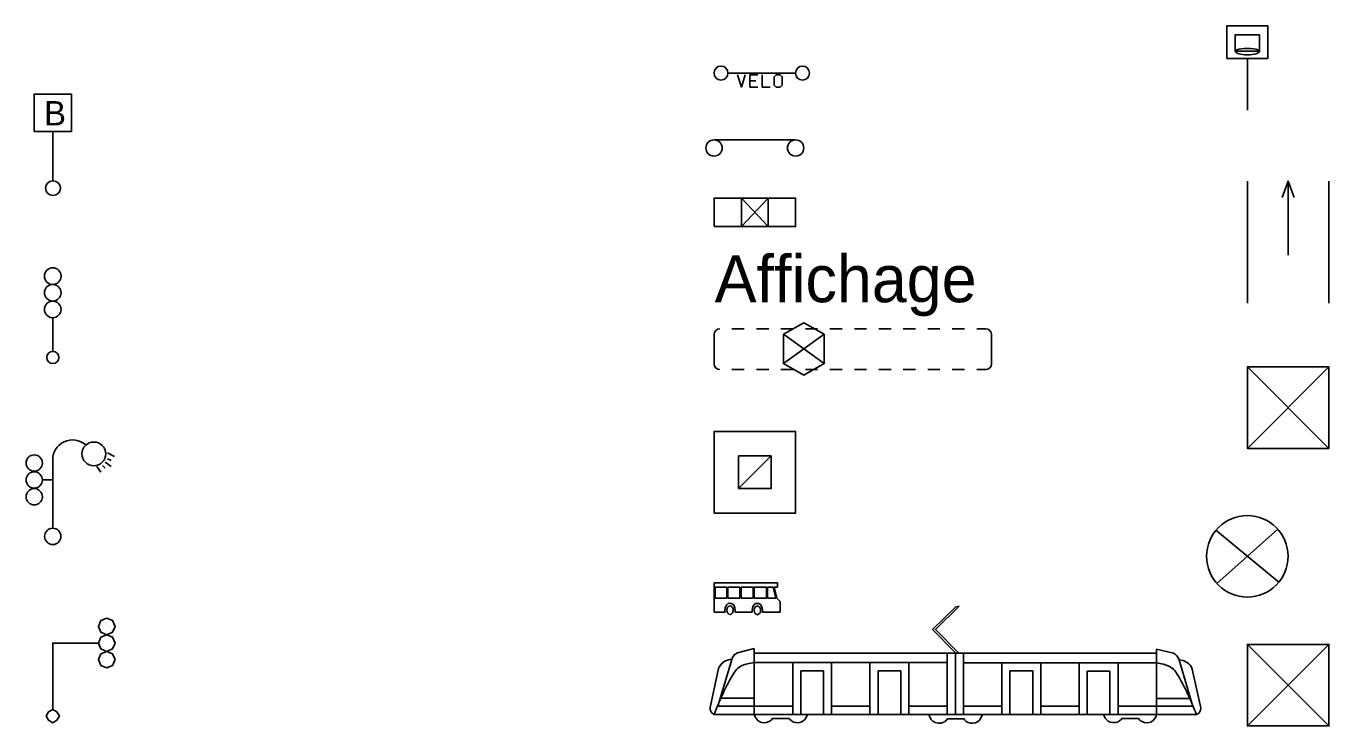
# Model space of a CAD drawing. Extents: x -1.5 to 18.2, y -66.6 to 3.3.
# Drawn here: x -0.17 to 15.81, y -42.95 to -34.37 of the extents above; entities that cross this region are included whole.
import ezdxf

# ---------------------------------------------------------------- set-up
doc = ezdxf.new("R2010")
doc.units = 0
for name, color, linetype in [('SOL_BATIMENT', 7, 'Continuous'), ('SOL_FEU_TRICOLORE_ET_PIETON', 7, 'Continuous'), ('SOL_JEUX', 7, 'Continuous'), ('SOL_MOBILIER_DIVERS', 7, 'Continuous'), ('SOL_MUR', 7, 'Continuous'), ('SOL_SIGNALISATION_VERTICALE', 7, 'Continuous')]:
    doc.layers.add(name, color=color, linetype=linetype)

# ---------------------------------------------------------------- blocks, each defined once
blk = doc.blocks.new('FEU_TRICOLORE')
blk.add_lwpolyline([(0, 0.075), (0, 0.489)])
for centre, radius in [((0, 0.999), 0.102), ((0, 0.795), 0.102), ((0, 0.591), 0.102), ((0.001, 0.001), 0.075)]:
    blk.add_circle(centre, radius)
blk = doc.blocks.new('FEU_CANDELABRE')
blk.add_line((0.001, 0.101), (0.001, 0.929))
for points in [[(0.673, 1.025), (0.756, 0.983)], [(0.539, 0.859), (0.59, 0.787)], [(0.611, 0.87), (0.642, 0.839)], [(0.642, 0.911), (0.715, 0.859)], [(0.673, 0.952), (0.715, 0.932)], [(0.001, 0.694), (-0.123, 0.694)]]:
    blk.add_lwpolyline(points)
for centre, radius in [((0.504, 1.013), 0.146), ((-0.227, 0.901), 0.1), ((-0.227, 0.694), 0.1), ((-0.227, 0.487), 0.1), ((0.001, 0.001), 0.1)]:
    blk.add_circle(centre, radius)
blk.add_arc((0.244, 0.941), 0.244, 48.1176, 182.659)
blk = doc.blocks.new('FEU_TRICOLORE_POTENCE')
for points in [[(0.764, 1.1), (0.734, 1.172), (0.663, 1.202), (0.591, 1.172), (0.561, 1.1), (0.591, 1.029), (0.663, 0.999), (0.734, 1.029), (0.764, 1.1)], [(0.764, 0.897), (0.734, 0.968), (0.663, 0.999), (0.591, 0.968), (0.561, 0.897), (0.591, 0.825), (0.663, 0.795), (0.734, 0.825), (0.764, 0.897)], [(0, 0.082), (0, 0.897), (0.561, 0.897)], [(0.764, 0.693), (0.734, 0.764), (0.663, 0.795), (0.591, 0.764), (0.561, 0.693), (0.591, 0.622), (0.663, 0.591), (0.734, 0.622), (0.764, 0.693)], [(0.082, 0), (0.051, 0.051), (0, 0.082), (-0.05, 0.051), (-0.081, 0), (-0.05, -0.05), (0, -0.081), (0.051, -0.05), (0.082, 0)]]:
    blk.add_lwpolyline(points)
blk = doc.blocks.new('ARCEAU_VELO')
blk.add_line((0.17, -0.01), (0.999, -0.01))
for points in [[(0.381, -0.032), (0.335, -0.182), (0.289, -0.032)], [(0.537, -0.182), (0.439, -0.182), (0.439, -0.032), (0.537, -0.032)], [(0.512, -0.106), (0.439, -0.106)], [(0.687, -0.182), (0.589, -0.182), (0.589, -0.032)], [(0.763, -0.032), (0.812, -0.032), (0.837, -0.056), (0.837, -0.159), (0.812, -0.182), (0.763, -0.182), (0.739, -0.159), (0.739, -0.056), (0.763, -0.032)]]:
    blk.add_lwpolyline(points)
for centre in [(0.085, -0.01), (1.085, -0.01)]:
    blk.add_circle(centre, 0.0854)
blk = doc.blocks.new('AFFICHAGE')
for p, q in [((-0.1, 0), (-0.1, 0)), ((0, 0.1), (1, 0.1))]:
    blk.add_line(p, q)
for centre in [(0, 0), (1, 0)]:
    blk.add_circle(centre, 0.1)
blk = doc.blocks.new('PANNEAU_PUB')
for points in [[(0, 0), (1, 0), (1, 0.35), (0, 0.35), (0, 0)], [(0.335, 0.35), (0.335, 0)], [(0.665, 0.35), (0.665, 0), (0.335, 0.35)], [(0.335, 0), (0.665, 0.35)]]:
    blk.add_lwpolyline(points)
blk = doc.blocks.new('PANNEAU_PUB_4X3')
for p, q in [((0.22, 0.503), (0.37, 0.503)), ((0.52, 0.503), (0.67, 0.503)), ((0.82, 0.503), (0.97, 0.503)), ((1.12, 0.503), (1.27, 0.503)), ((1.42, 0.503), (1.57, 0.503)), ((1.72, 0.503), (1.87, 0.503)), ((2.02, 0.503), (2.17, 0.503)), ((2.32, 0.503), (2.47, 0.503)), ((2.62, 0.503), (2.77, 0.503)), ((2.92, 0.503), (3.07, 0.503)), ((3.22, 0.503), (3.331, 0.503)), ((0.001, 0.073), (0.001, 0.437)), ((0.001, 0.261), (0.001, 0.433)), ((0.851, 0.437), (1.351, 0.077)), ((1.351, 0.437), (0.851, 0.077)), ((3.401, 0.073), (3.401, 0.433)), ((0.22, 0.003), (0.37, 0.003)), ((0.52, 0.003), (0.67, 0.003)), ((0.82, 0.003), (0.97, 0.003)), ((1.12, 0.003), (1.27, 0.003)), ((1.42, 0.003), (1.57, 0.003)), ((1.72, 0.003), (1.87, 0.003)), ((2.02, 0.003), (2.17, 0.003)), ((2.32, 0.003), (2.47, 0.003)), ((2.62, 0.003), (2.77, 0.003)), ((2.92, 0.003), (3.07, 0.003)), ((3.22, 0.003), (3.331, 0.003))]:
    blk.add_line(p, q)
blk.add_lwpolyline([(0.851, 0.437), (1.101, 0.577), (1.351, 0.437), (1.351, 0.077), (1.101, -0.063), (0.851, 0.077)], close=True)
for centre, start, end in [((0.071, 0.433), 90, 179.9999), ((3.331, 0.433), 0, 90), ((0.071, 0.073), 180, 270), ((3.331, 0.073), 270, 0)]:
    blk.add_arc(centre, 0.07, start, end)
blk.add_text('Affichage', height=0.576).set_placement((0.008, 0.83))
blk = doc.blocks.new('CONTAINER_RECYCLAGE_ENTERRE')
blk.add_line((0.7, 0.7), (0.3, 0.3))
for points in [[(0, 0), (1, 0), (1, 1), (0, 1)], [(0.3, 0.3), (0.7, 0.3), (0.7, 0.7), (0.3, 0.7)]]:
    blk.add_lwpolyline(points, close=True)
blk = doc.blocks.new('SYMBOLE_BUS')
for p, q in [((0.78, 0.357), (0, 0.357)), ((0, 0.357), (0, 0.303)), ((0.78, 0.303), (0.78, 0.357)), ((0, 0.303), (0, 0.169)), ((0, -0.005), (0, 0.169)), ((0.012, 0.169), (0.012, 0.303)), ((0.012, 0.303), (0.155, 0.303)), ((0.012, 0.169), (0.155, 0.169)), ((0.155, 0.169), (0.155, 0.303)), ((0.168, 0.303), (0.168, 0.169)), ((0.168, 0.303), (0.318, 0.303)), ((0.168, 0.169), (0.318, 0.169)), ((0.318, 0.169), (0.318, 0.303)), ((0.331, 0.303), (0.331, 0.169)), ((0.331, 0.303), (0.48, 0.303)), ((0.331, 0.169), (0.48, 0.169)), ((0.48, 0.169), (0.48, 0.303)), ((0.492, 0.303), (0.492, 0.169)), ((0.492, 0.303), (0.643, 0.303)), ((0.492, 0.169), (0.643, 0.169)), ((0.643, 0.303), (0.643, 0.169)), ((0.655, 0.169), (0.655, 0.303)), ((0.655, 0.303), (0.724, 0.303)), ((0.655, 0.169), (0.757, 0.169)), ((0.757, 0.169), (0.724, 0.303)), ((0.737, 0.303), (0.77, 0.167)), ((0.737, 0.303), (0.78, 0.303)), ((0.77, 0.167), (0.812, 0.126)), ((0.812, 0.126), (0.812, -0.005)), ((0.135, -0.005), (0, -0.005)), ((0.469, -0.005), (0.258, -0.005)), ((0.812, -0.005), (0.592, -0.005))]:
    blk.add_line(p, q)
for centre, start_param, end_param in [((0.196, 0.021), 5.739303, 8.162658), ((0.196, 0.021), 4.403713, 5.739695), ((0.531, 0.019), 4.43676, 8.12961)]:
    blk.add_ellipse(centre, major_axis=(0, 0.0858), ratio=0.74787, start_param=start_param, end_param=end_param)
for centre in [(0.196, 0.021), (0.531, 0.019)]:
    blk.add_ellipse(centre, major_axis=(0, 0.0532), ratio=0.74787)
blk = doc.blocks.new('SYMBOLE_TRAM')
for p, q in [((2.964, 1.321), (3.006, 1.328)), ((0.287, 0.756), (0.494, 0.807)), ((0.494, 0.751), (0.494, 0.807)), ((5.426, 0.751), (5.426, 0.801)), ((5.426, 0.801), (5.631, 0.75)), ((0.048, 0.1), (0.223, 0.688)), ((2.859, 0), (2.859, 0.751)), ((2.959, 0), (2.959, 0.751)), ((3.059, 0), (3.059, 0.751)), ((5.696, 0.682), (5.868, 0.096)), ((-0.049, 0.086), (0.056, 0.563)), ((-0.049, 0.086), (0.056, 0.563)), ((0.493, 0.635), (2.859, 0.635)), ((0.964, 0.635), (0.964, 0)), ((1.342, 0.535), (1.064, 0.535)), ((1.064, 0.535), (1.064, 0)), ((1.342, 0), (1.342, 0.535)), ((1.442, 0), (1.442, 0.635)), ((1.911, 0.635), (1.911, 0)), ((2.289, 0.535), (2.011, 0.535)), ((2.011, 0.535), (2.011, 0)), ((2.289, 0), (2.289, 0.535)), ((2.389, 0), (2.389, 0.635)), ((3.059, 0.634), (5.426, 0.634)), ((3.528, 0.634), (3.528, 0)), ((3.907, 0.533), (3.628, 0.533)), ((3.628, 0.533), (3.628, 0)), ((3.907, 0), (3.907, 0.533)), ((4.006, 0), (4.006, 0.634)), ((4.476, 0.634), (4.476, 0)), ((4.854, 0.531), (4.576, 0.531)), ((4.576, 0.531), (4.576, 0)), ((4.854, 0), (4.854, 0.531)), ((4.955, 0), (4.955, 0.634)), ((5.967, 0.08), (5.863, 0.557)), ((5.863, 0.557), (5.967, 0.08)), ((5.426, 0.195), (5.821, 0.195)), ((0.494, 0), (0, 0)), ((0.048, 0.1), (0.964, 0.1)), ((1.064, 0), (1.342, 0)), ((1.441, 0.1), (1.911, 0.1)), ((2.011, 0), (2.289, 0)), ((2.389, 0.1), (2.859, 0.1)), ((3.059, 0.1), (3.529, 0.1)), ((4.006, 0.1), (4.476, 0.1)), ((4.955, 0.1), (5.866, 0.1)), ((5.426, 0), (5.914, 0))]:
    blk.add_line(p, q)
for points in [[(2.959, 0.756), (2.679, 1.041), (2.964, 1.321)], [(2.995, 0.756), (2.714, 1.041), (3.006, 1.328)], [(0.096, 0.2), (0.494, 0.2)], [(0.494, 0), (0.503, -0.028), (0.519, -0.056), (0.541, -0.077), (0.569, -0.094), (0.605, -0.103), (0.642, -0.1), (0.677, -0.087), (0.699, -0.07), (0.716, -0.05), (0.717, -0.05), (0.922, -0.05), (0.927, -0.059), (0.948, -0.078), (0.975, -0.094), (1.001, -0.101), (1.031, -0.103), (1.065, -0.095), (1.088, -0.083), (1.106, -0.07), (1.126, -0.046), (1.146, 0)], [(2.635, 0), (2.646, -0.035), (2.662, -0.062), (2.684, -0.083), (2.712, -0.1), (2.748, -0.109), (2.785, -0.107), (2.819, -0.093), (2.842, -0.077), (2.859, -0.057), (2.859, -0.056), (3.065, -0.056), (3.07, -0.066), (3.09, -0.085), (3.117, -0.1), (3.143, -0.107), (3.174, -0.109), (3.207, -0.102), (3.231, -0.09), (3.249, -0.076), (3.268, -0.053), (3.292, 0)], [(5.426, 0), (5.417, -0.028), (5.401, -0.056), (5.379, -0.077), (5.351, -0.093), (5.315, -0.102), (5.278, -0.1), (5.243, -0.086), (5.22, -0.07), (5.204, -0.05), (5.203, -0.049), (4.998, -0.049), (4.993, -0.058), (4.972, -0.077), (4.945, -0.093), (4.919, -0.1), (4.889, -0.101), (4.855, -0.094), (4.832, -0.082), (4.814, -0.068), (4.794, -0.045), (4.775, 0)]]:
    blk.add_lwpolyline(points)
blk.add_lwpolyline([(0.494, 0), (5.426, 0), (5.426, 0.751), (0.494, 0.751)], close=True)
for centre, radius, start, end in [((0.222, 0.496), 0.18, 90.9776, 158.0859), ((0.222, 0.496), 0.18, 90.9776, 158.0859), ((0.329, 0.653), 0.111, 111.6368, 161.3709), ((5.59, 0.647), 0.111, 18.5065, 68.2407), ((5.696, 0.49), 0.18, 21.7916, 88.8952), ((5.696, 0.49), 0.18, 21.7916, 88.8952), ((0.032, 0.075), 0.082, 172.5135, 246.9011), ((0.032, 0.075), 0.082, 172.5135, 246.9011), ((5.888, 0.074), 0.0789, 289.5292, 3.9168), ((5.888, 0.074), 0.0789, 289.5292, 3.9168)]:
    blk.add_arc(centre, radius, start, end)
for points in [[(0.493, 0.635), (0.411, 0.621), (0.288, 0.563), (0.244, 0.506), (0, 0)], [(5.426, 0.634), (5.508, 0.615), (5.631, 0.557), (5.674, 0.5), (5.914, 0)]]:
    blk.add_spline(points, degree=3)
blk = doc.blocks.new('PANNEAU_BASKET')
blk.add_line((0, 0.632), (0, 0))
for points in [[(-0.25, 0.632), (0.25, 0.632), (0.25, 1.032), (-0.25, 1.032)], [(0, 0.722), (0.15, 0.722), (0.15, 0.922), (-0.15, 0.922), (-0.15, 0.722)]]:
    blk.add_lwpolyline(points, close=True)
for ratio, start_param, end_param in [(0.230019, 0, 3.141593), (0.291134, 3.141593, 6.283185)]:
    blk.add_ellipse((0, 0.722), major_axis=(0.15, 0), ratio=ratio, start_param=start_param, end_param=end_param)
blk = doc.blocks.new('ENTREE_BATIMENT')
for points in [[(0, 0), (0, 1.5)], [(0.5, 1.5), (0.425, 1.299)], [(0.5, 0.591), (0.5, 1.5), (0.575, 1.299)], [(1, 0), (1, 1.5)]]:
    blk.add_lwpolyline(points)
blk = doc.blocks.new('PILIER_BATI_CARRE')
for points in [[(0, 0), (1, 0), (1, 1), (0, 1), (0, 0), (1, 1)], [(0, 1), (1, 0)]]:
    blk.add_lwpolyline(points)
blk = doc.blocks.new('PILIER_BATI_ROND')
for p, q in [((0.374, 0.332), (-0.374, -0.332)), ((-0.385, 0.319), (0.385, -0.319))]:
    blk.add_line(p, q)
blk.add_circle((0, 0), 0.5)
blk = doc.blocks.new('PILIER_MUR_CARRE')
for points in [[(0, 0), (1, 0), (1, 1), (0, 1), (0, 0), (1, 1)], [(0, 1), (1, 0)]]:
    blk.add_lwpolyline(points)
blk = doc.blocks.new('PANNEAU_BUS')
for points in [[(-0.229, 0.697), (0.229, 0.697), (0.229, 1.155), (-0.229, 1.155), (-0.229, 0.697)], [(0, 0.091), (0, 0.697)]]:
    blk.add_lwpolyline(points)
blk.add_circle((0.002, 0), 0.0907)
blk.add_text('B', height=0.3).set_placement((-0.106, 0.769))

msp = doc.modelspace()

# ---------------------------------------------------------------- block references
at = {"layer": 'SOL_BATIMENT'}
for name, p in [('ENTREE_BATIMENT', (14.805, -37.768)), ('PILIER_BATI_CARRE', (14.805, -39.549)), ('PILIER_BATI_ROND', (14.805, -40.872))]:
    msp.add_blockref(name, p, dxfattribs=at)
at = {"layer": 'SOL_FEU_TRICOLORE_ET_PIETON'}
for name, p in [('FEU_TRICOLORE', (0.16, -38.434)), ('FEU_CANDELABRE', (0.16, -40.629)), ('FEU_TRICOLORE_POTENCE', (0.16, -42.833))]:
    msp.add_blockref(name, p, dxfattribs=at)
at = {"layer": 'SOL_JEUX'}
msp.add_blockref('PANNEAU_BASKET', (14.805, -35.398), dxfattribs=at)
at = {"layer": 'SOL_MOBILIER_DIVERS'}
for name, p in [('ARCEAU_VELO', (8.267, -34.934)), ('AFFICHAGE', (8.267, -35.863)), ('PANNEAU_PUB', (8.267, -36.827)), ('PANNEAU_PUB_4X3', (8.267, -38.585)), ('CONTAINER_RECYCLAGE_ENTERRE', (8.267, -40.341)), ('SYMBOLE_BUS', (8.267, -41.554)), ('SYMBOLE_TRAM', (8.267, -42.812))]:
    msp.add_blockref(name, p, dxfattribs=at)
at = {"layer": 'SOL_MUR'}
msp.add_blockref('PILIER_MUR_CARRE', (14.805, -42.954), dxfattribs=at)
at = {"layer": 'SOL_SIGNALISATION_VERTICALE'}
msp.add_blockref('PANNEAU_BUS', (0.161, -36.356), dxfattribs=at)

doc.saveas('drawing.dxf')
